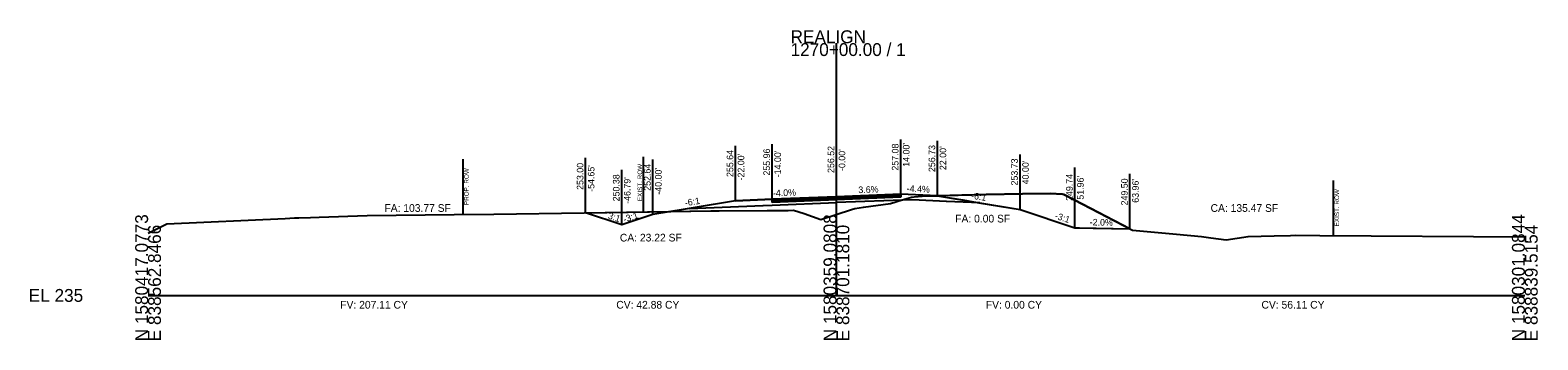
# Model space of a CAD drawing. Extents: x -26 to 6303, y -16 to 9563.
# Drawn here: x 4974.3 to 5302.8, y 3490.3 to 3557.8 of the extents above; entities that cross this region are included whole.
import ezdxf

# ---------------------------------------------------------------- set-up
doc = ezdxf.new("R2010")
doc.units = 0
for name, color, linetype in [('ASPHALT_19MM1', 7, 'Continuous'), ('ASPHALT_9_5MM1', 7, 'Continuous'), ('CONST_DCH', 7, 'Continuous'), ('CONST_LV3', 7, 'Continuous'), ('Default', 7, 'Continuous'), ('Draft_XS_Grid', 7, 'Continuous'), ('DTM_TEMP_DROP', 7, 'Continuous'), ('DTM_X_GROUND', 7, 'Continuous'), ('X_TRANS_EOP', 7, 'Continuous'), ('XS_CELL', 7, 'Continuous'), ('XS_M_SHAPES_EARTHWORK', 7, 'Continuous'), ('XS_P_ASPHALT', 7, 'Continuous'), ('XS_P_GROUND', 7, 'Continuous'), ('XS_P_ROW', 7, 'Continuous'), ('XS_P_SHOULDER', 7, 'Continuous'), ('XS_P_SUBGRADE_GRANULAR', 7, 'Continuous'), ('XS_P_TX_CLEARZONE', 7, 'Continuous'), ('XS_P_TX_FS_BS', 7, 'Continuous'), ('XS_SHEET_EW_TX_AREA', 7, 'Continuous'), ('XS_SHEET_EW_TX_VOLUME', 7, 'Continuous'), ('XS_X_ROW', 7, 'Continuous')]:
    doc.layers.add(name, color=color, linetype=linetype)

msp = doc.modelspace()

# ---------------------------------------------------------------- linework, layer by layer
at = {"layer": 'ASPHALT_19MM1'}
msp.add_lwpolyline([(5136, 3520.63), (5136, 3520.36), (5150, 3520.92), (5150, 3520.92), (5164, 3521.48), (5164, 3521.48), (5164, 3521.75), (5164, 3521.75), (5164, 3521.75), (5150, 3521.19), (5150, 3521.19), (5136, 3520.63), (5136, 3520.63)], dxfattribs=at)
at = {"layer": 'ASPHALT_9_5MM1'}
msp.add_lwpolyline([(5136, 3520.96), (5136, 3520.84), (5150, 3521.4), (5150, 3521.4), (5164, 3521.96), (5164, 3521.96), (5164, 3522.08), (5164, 3522.08), (5164, 3522.08), (5150, 3521.52), (5150, 3521.52), (5136, 3520.96), (5136, 3520.96)], dxfattribs=at)
at = {"layer": 'CONST_LV3'}
for points in [[(5164, 3522.08), (5150, 3521.52), (5150, 3521.52)], [(5172, 3521.73), (5164, 3522.08), (5164, 3522.08)], [(5117.97, 3518.97), (5110, 3517.64)]]:
    msp.add_lwpolyline(points, dxfattribs=at)
at = {"layer": 'Default'}
msp.add_lwpolyline([(5136, 3520.84), (5136, 3520.63), (5150, 3521.19), (5150, 3521.19), (5164, 3521.75), (5164, 3521.75), (5164, 3521.96), (5164, 3521.96), (5164, 3521.96), (5150, 3521.4), (5150, 3521.4), (5136, 3520.84), (5136, 3520.84)], dxfattribs=at)
at = {"layer": 'DTM_X_GROUND'}
msp.add_lwpolyline([(5000, 3513.55), (5004.09, 3515.61), (5029.86, 3516.8), (5031.89, 3516.88), (5032.82, 3516.91), (5035.39, 3517.01), (5037.25, 3517.07), (5047.71, 3517.44), (5066.69, 3517.67), (5075.31, 3517.73), (5095.02, 3517.99), (5122.62, 3518.42), (5124.47, 3518.44), (5134.93, 3518.49), (5139.46, 3518.55), (5140.61, 3518.57), (5142.99, 3517.86), (5146.6, 3516.54), (5153.31, 3518.74), (5154.01, 3518.96), (5155.89, 3519.22), (5161.75, 3520.03), (5164.31, 3520.81), (5166.37, 3521.44), (5166.96, 3521.49), (5168.66, 3521.65), (5173.48, 3521.76), (5182.66, 3521.98), (5190.51, 3522.13), (5196.6, 3522.24), (5199.24, 3522.05), (5199.52, 3522.03), (5201.81, 3520.84), (5214.5, 3514.22), (5224.08, 3513.34), (5229.57, 3512.86), (5231.61, 3512.57), (5234.94, 3512.09), (5237.32, 3512.45), (5239.73, 3512.82), (5245.37, 3512.99), (5248.93, 3513.09), (5250.14, 3513.13), (5255.36, 3513.05), (5300, 3512.78)], dxfattribs=at)
at = {"layer": 'XS_CELL'}
for p, q in [((5150, 3500), (5150, 3555)), ((5000, 3500), (5150, 3500)), ((5150, 3500), (5300, 3500))]:
    msp.add_line(p, q, dxfattribs=at)
at = {"layer": 'XS_M_SHAPES_EARTHWORK'}
for points in [[(5113.88, 3518.29), (5122.62, 3518.42), (5124.47, 3518.44), (5134.93, 3518.49), (5139.46, 3518.55), (5140.61, 3518.57), (5142.99, 3517.86), (5146.6, 3516.54), (5153.31, 3518.74), (5154.01, 3518.96), (5155.89, 3519.22), (5161.75, 3520.03), (5164.31, 3520.81), (5166.37, 3521.44), (5166.96, 3521.49), (5168.66, 3521.65), (5172, 3521.73), (5164, 3522.08), (5164, 3521.96), (5164, 3521.75), (5164, 3521.48), (5150, 3520.92), (5136, 3520.36), (5136, 3520.63), (5136, 3520.84), (5136, 3520.96), (5128, 3520.64), (5117.97, 3518.97)], [(5095.35, 3518), (5113.88, 3518.29), (5110, 3517.64), (5103.21, 3515.38)]]:
    msp.add_lwpolyline(points, close=True, dxfattribs=at)
at = {"layer": 'XS_P_GROUND'}
for points in [[(5128, 3520.64), (5110, 3517.64), (5103.21, 3515.38)], [(5172, 3521.73), (5172, 3521.73)], [(5172, 3521.73), (5190, 3518.73), (5201.96, 3514.74)], [(5103.21, 3515.38), (5095.35, 3518)], [(5201.96, 3514.74), (5202.96, 3514.72)], [(5202.96, 3514.72), (5213.96, 3514.5)]]:
    msp.add_lwpolyline(points, dxfattribs=at)
at = {"layer": 'XS_P_ROW'}
msp.add_line((5068.66, 3517.69), (5068.66, 3529.69), dxfattribs=at)
at = {"layer": 'XS_P_SHOULDER'}
for points in [[(5172, 3521.73), (5164, 3522.08), (5164, 3522.08)], [(5128, 3520.64), (5136, 3520.96), (5136, 3520.96)]]:
    msp.add_lwpolyline(points, dxfattribs=at)
at = {"layer": 'XS_P_SUBGRADE_GRANULAR'}
for points in [[(5117.97, 3518.97), (5134, 3519.61), (5134, 3519.61), (5136, 3519.69), (5136, 3519.69)], [(5136, 3519.69), (5150, 3520.25), (5150, 3520.25)], [(5166.5, 3520.87), (5166.5, 3520.87), (5150, 3520.25)], [(5181.26, 3520.18), (5174, 3520.47), (5174, 3520.47), (5166.5, 3520.87), (5166.5, 3520.87)]]:
    msp.add_lwpolyline(points, dxfattribs=at)
at = {"layer": 'XS_P_TX_CLEARZONE'}
for p, q in [((5128, 3520.64), (5128, 3532.64)), ((5136, 3520.96), (5136, 3532.96)), ((5150, 3521.52), (5150, 3533.52)), ((5164, 3522.02), (5164, 3534.02)), ((5172, 3521.73), (5172, 3533.73)), ((5172, 3521.73), (5172, 3533.73)), ((5095.35, 3518), (5095.35, 3530)), ((5110, 3517.64), (5110, 3529.64)), ((5190, 3518.73), (5190, 3530.73)), ((5103.21, 3515.38), (5103.21, 3527.38)), ((5201.96, 3514.74), (5201.96, 3527.92)), ((5213.96, 3514.5), (5213.96, 3526.5))]:
    msp.add_line(p, q, dxfattribs=at)
at = {"layer": 'XS_P_TX_FS_BS'}
for p, q in [((5172, 3521.72), (5177.51, 3520.83)), ((5190, 3518.72), (5201.96, 3514.74)), ((5201.96, 3514.74), (5213.96, 3514.5))]:
    msp.add_line(p, q, dxfattribs=at)
for points in [[(5213.96, 3514.5), (5201.81, 3520.84), (5199.52, 3522.03), (5199.24, 3522.05), (5196.6, 3522.24), (5190.51, 3522.13), (5182.66, 3521.98), (5172, 3521.72)], [(5177.51, 3520.83), (5181, 3520.22), (5190, 3518.72)]]:
    msp.add_lwpolyline(points, dxfattribs=at)
at = {"layer": 'XS_X_ROW'}
for p, q in [((5107.97, 3518.2), (5107.97, 3530.2)), ((5258.33, 3513.04), (5258.33, 3525.04))]:
    msp.add_line(p, q, dxfattribs=at)

# ---------------------------------------------------------------- texts
at = {"layer": 'CONST_DCH'}
for p in [(5171.92, 3521.61), (5189.92, 3518.61)]:
    msp.add_text('X', height=0.24, dxfattribs=at).set_placement(p)
at = {"layer": 'Draft_XS_Grid'}
msp.add_text('-', height=0.0001, dxfattribs=at).set_placement((5000, 3500))
at = {"layer": 'DTM_TEMP_DROP'}
for p in [(5163.92, 3521.96), (5135.92, 3520.84), (5149.92, 3521.4)]:
    msp.add_text('X', height=0.24, dxfattribs=at).set_placement(p)
at = {"layer": 'X_TRANS_EOP'}
for p in [(5171.92, 3521.61), (5095.27, 3517.88)]:
    msp.add_text('X', height=0.24, dxfattribs=at).set_placement(p)
at = {"layer": 'XS_CELL'}
for s, p in [('1270+00.00 / 1', (5140, 3552.2)), ('REALIGN', (5140, 3555)), ('EL 235', (4974, 3498.6))]:
    msp.add_text(s, height=2.8, dxfattribs=at).set_placement(p)
for s, p in [('N 1580417.0773', (5000, 3490)), ('N 1580359.0808', (5150, 3490)), ('N 1580301.0844', (5300, 3490)), ('E 838562.8466', (5002.8, 3490)), ('E 838701.1810', (5152.8, 3490)), ('E 838839.5154', (5302.8, 3490))]:
    msp.add_text(s, height=2.8, rotation=90, dxfattribs=at).set_placement(p)
at = {"layer": 'XS_P_ASPHALT'}
msp.add_text('X', height=0.24, dxfattribs=at).set_placement((5109.92, 3517.52))
at = {"layer": 'XS_P_GROUND'}
msp.add_text('X', height=0.24, dxfattribs=at).set_placement((5171.92, 3521.61))
at = {"layer": 'XS_P_ROW'}
msp.add_text('PROP. ROW', height=1, rotation=90, dxfattribs=at).set_placement((5069.86, 3519.69))
at = {"layer": 'XS_P_SHOULDER'}
for p in [(5127.92, 3520.52), (5171.92, 3521.61), (5201.89, 3514.62)]:
    msp.add_text('X', height=0.24, dxfattribs=at).set_placement(p)
at = {"layer": 'XS_P_SUBGRADE_GRANULAR'}
for p in [(5171.92, 3521.61), (5103.13, 3515.26), (5213.88, 3514.38)]:
    msp.add_text('X', height=0.24, dxfattribs=at).set_placement(p)
at = {"layer": 'XS_P_TX_CLEARZONE'}
for s, p in [('255.96', (5135.52, 3526.13)), ('256.52', (5149.52, 3526.7)), ("-0.00'", (5151.92, 3527.13)), ('257.08', (5163.52, 3527.21)), ("14.00'", (5165.92, 3528.05)), ('256.73', (5171.52, 3526.9)), ("22.00'", (5173.92, 3527.33)), ('253.00', (5094.87, 3523.01)), ('252.64', (5109.52, 3522.82)), ('255.64', (5127.52, 3525.82)), ("-22.00'", (5129.92, 3525.07)), ("-14.00'", (5137.92, 3525.75)), ('253.73', (5189.52, 3523.97)), ("40.00'", (5191.92, 3524.22)), ("-54.65'", (5097.27, 3522.59)), ('250.38', (5102.73, 3520.51)), ("-46.79'", (5105.13, 3519.97)), ("-40.00'", (5111.92, 3521.96)), ('249.74', (5201.48, 3520.6)), ("51.96'", (5203.88, 3520.87)), ('249.50', (5213.48, 3519.62)), ("63.96'", (5215.88, 3520.2))]:
    msp.add_text(s, height=1.44, rotation=90, dxfattribs=at).set_placement(p)
at = {"layer": 'XS_P_TX_FS_BS'}
for s, rotation, p in [('-4.0%', 2.2906, (5136.18, 3521.57)), ('3.6%', 2.0456, (5154.8, 3522.29)), ('-4.4%', 357.4524, (5165.29, 3522.62)), ('-6:1', 350.5377, (5179.28, 3521.12)), ('-6:1', 9.4642, (5117.08, 3519.43)), ('3:1', 341.5651, (5100.1, 3516.79)), ('-3:1', 18.4332, (5103.8, 3515.84)), ('-3:1', 341.5651, (5197.46, 3516.79)), ('-2.0%', 358.8542, (5205.18, 3515.27))]:
    msp.add_text(s, height=1.44, rotation=rotation, dxfattribs=at).set_placement(p)
at = {"layer": 'XS_SHEET_EW_TX_AREA'}
for s, p in [('FA: 103.77 SF', (5051.5, 3518.22)), ('CA: 135.47 SF', (5231.53, 3518.22)), ('FA: 0.00 SF', (5175.88, 3515.9)), ('CA: 23.22 SF', (5102.81, 3511.76))]:
    msp.add_text(s, height=1.68, dxfattribs=at).set_placement(p)
at = {"layer": 'XS_SHEET_EW_TX_VOLUME'}
for s, p in [('FV: 207.11 CY', (5041.88, 3497.12)), ('CV: 42.88 CY', (5102.03, 3497.12)), ('FV: 0.00 CY', (5182.55, 3497.12)), ('CV: 56.11 CY', (5242.62, 3497.12))]:
    msp.add_text(s, height=1.68, dxfattribs=at).set_placement(p)
at = {"layer": 'XS_X_ROW'}
for p in [(5107.66, 3520.56), (5259.53, 3515.04)]:
    msp.add_text('EXIST. ROW', height=1, rotation=90, dxfattribs=at).set_placement(p)

doc.saveas('drawing.dxf')
